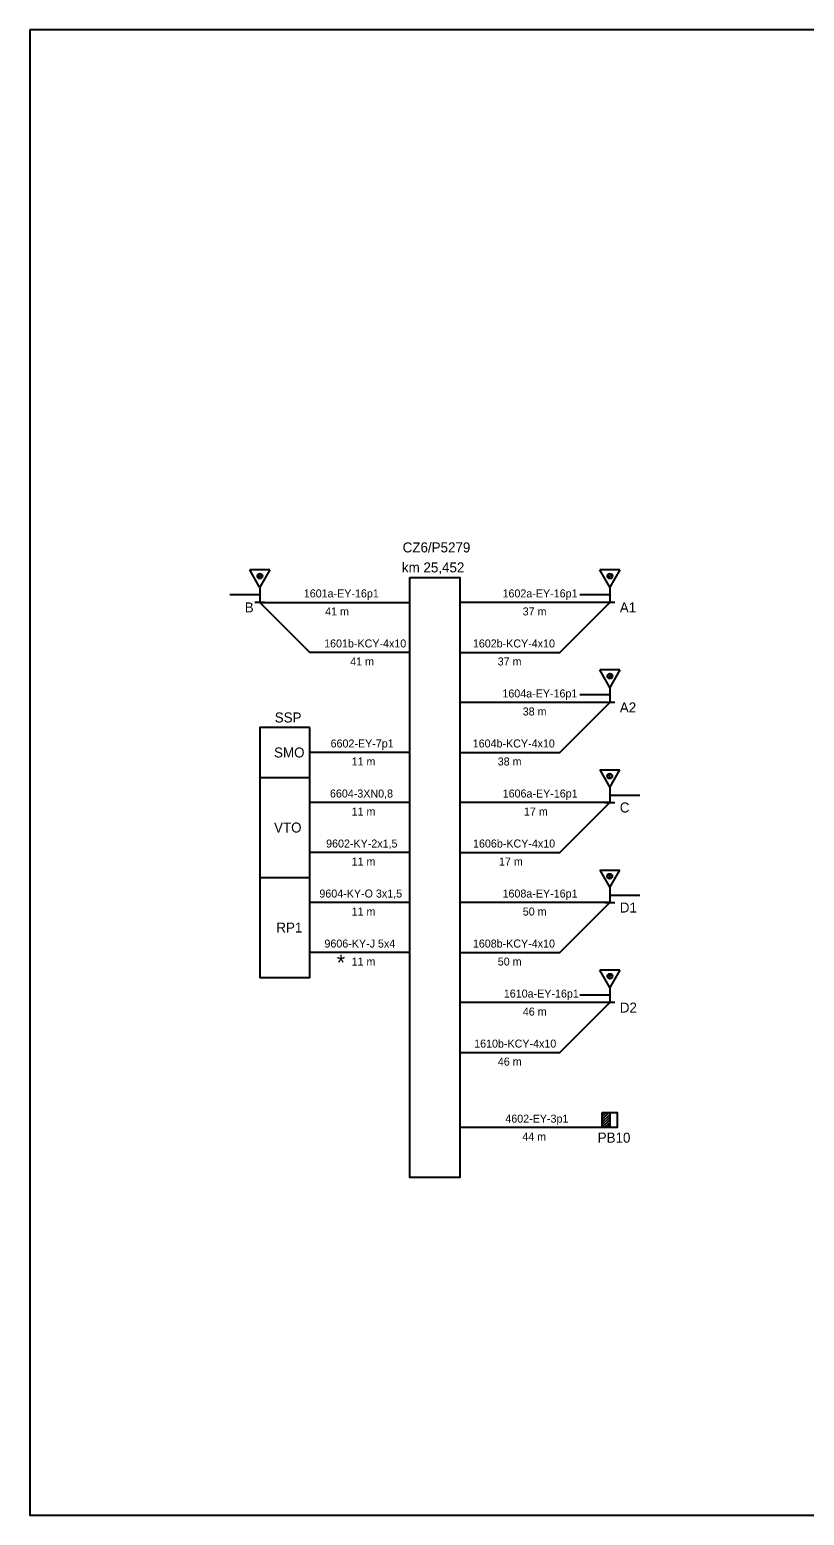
# Model space of a CAD drawing. Extents: x -650084 to -649664, y -1160055 to -1159758.
# Drawn here: x -650084 to -649929.1, y -1160054.5 to -1159757.5 of the extents above; entities that cross this region are included whole.
import ezdxf

# ---------------------------------------------------------------- set-up
doc = ezdxf.new("R2010")
doc.units = 0
doc.layers.add('Rámečky-tisk', color=7, linetype='Continuous')
doc.layers.add('Vrstva 1', color=7, linetype='Continuous')

msp = doc.modelspace()

# ---------------------------------------------------------------- linework, layer by layer
at = {"layer": 'Rámečky-tisk'}
msp.add_line((-649664, -1159757.5), (-650084, -1159757.5), dxfattribs=at)
msp.add_lwpolyline([(-650084, -1159757.5), (-650084, -1160054.5), (-649664, -1160054.5)], dxfattribs=at)
at = {"layer": 'Vrstva 1'}
for p, q in [((-650038.02, -1159868.98), (-650040, -1159865.5)), ((-650036, -1159865.5), (-650040, -1159865.5)), ((-650038.48, -1159866.76), (-650037.95, -1159866.23)), ((-650038.3, -1159867.11), (-650037.6, -1159866.41)), ((-650036, -1159865.5), (-650037.98, -1159868.98)), ((-650037.87, -1159867.21), (-650037.5, -1159866.84)), ((-649968.02, -1159868.98), (-649970, -1159865.5)), ((-649966, -1159865.5), (-649970, -1159865.5)), ((-649968.48, -1159866.76), (-649967.95, -1159866.23)), ((-649968.3, -1159867.11), (-649967.6, -1159866.41)), ((-649966, -1159865.5), (-649967.98, -1159868.98)), ((-649967.87, -1159867.21), (-649967.5, -1159866.84)), ((-650038, -1159870.5), (-650044, -1159870.5)), ((-650038, -1159869), (-650038, -1159872)), ((-649968, -1159870.5), (-649974, -1159870.5)), ((-649968, -1159869), (-649968, -1159872)), ((-650037, -1159872), (-650039, -1159872)), ((-650038, -1159872), (-650008, -1159872)), ((-649968, -1159872), (-649998, -1159872)), ((-649967, -1159872), (-649969, -1159872)), ((-649968.02, -1159888.98), (-649970, -1159885.5)), ((-649966, -1159885.5), (-649970, -1159885.5)), ((-649966, -1159885.5), (-649967.98, -1159888.98)), ((-649968.48, -1159886.76), (-649967.95, -1159886.23)), ((-649968.3, -1159887.11), (-649967.6, -1159886.41)), ((-649967.87, -1159887.21), (-649967.5, -1159886.84)), ((-649968, -1159890.5), (-649974, -1159890.5)), ((-649968, -1159889), (-649968, -1159892)), ((-649968, -1159892), (-649998, -1159892)), ((-649967, -1159892), (-649969, -1159892)), ((-650008, -1159902), (-650028, -1159902)), ((-649970, -1159905.5), (-649966, -1159905.5)), ((-649970, -1159905.5), (-649968.02, -1159908.98)), ((-649967.7, -1159907.11), (-649968.4, -1159906.41)), ((-649967.52, -1159906.76), (-649968.05, -1159906.23)), ((-649967.98, -1159908.98), (-649966, -1159905.5)), ((-650038, -1159907), (-650028, -1159907)), ((-649968.13, -1159907.21), (-649968.5, -1159906.84)), ((-649968, -1159909), (-649968, -1159912)), ((-650008, -1159912), (-650028, -1159912)), ((-649968, -1159912), (-649998, -1159912)), ((-649969, -1159912), (-649967, -1159912)), ((-649968, -1159910.5), (-649962, -1159910.5)), ((-650008, -1159922), (-650028, -1159922)), ((-650038, -1159927), (-650028, -1159927)), ((-649970, -1159925.5), (-649966, -1159925.5)), ((-649970, -1159925.5), (-649968.02, -1159928.98)), ((-649968.13, -1159927.21), (-649968.5, -1159926.84)), ((-649967.7, -1159927.11), (-649968.4, -1159926.41)), ((-649967.52, -1159926.76), (-649968.05, -1159926.23)), ((-649967.98, -1159928.98), (-649966, -1159925.5)), ((-649968, -1159929), (-649968, -1159932)), ((-649968, -1159930.5), (-649962, -1159930.5)), ((-650008, -1159932), (-650028, -1159932)), ((-649968, -1159932), (-649998, -1159932)), ((-649969, -1159932), (-649967, -1159932)), ((-650008, -1159942), (-650028, -1159942)), ((-649968.02, -1159948.98), (-649970, -1159945.5)), ((-649966, -1159945.5), (-649970, -1159945.5)), ((-649968.48, -1159946.76), (-649967.95, -1159946.23)), ((-649968.3, -1159947.11), (-649967.6, -1159946.41)), ((-649966, -1159945.5), (-649967.98, -1159948.98)), ((-649967.87, -1159947.21), (-649967.5, -1159946.84)), ((-649968, -1159950.5), (-649974, -1159950.5)), ((-649968, -1159949), (-649968, -1159952)), ((-649968, -1159952), (-649998, -1159952)), ((-649967, -1159952), (-649969, -1159952)), ((-649969.5, -1159974.26), (-649969.24, -1159974)), ((-649969.5, -1159974.79), (-649968.71, -1159974)), ((-649969.5, -1159975.32), (-649968.18, -1159974)), ((-649969.5, -1159975.85), (-649968, -1159974.35)), ((-649969.5, -1159976.38), (-649968, -1159974.88)), ((-649968, -1159977), (-649998, -1159977)), ((-649969.5, -1159976.91), (-649968, -1159975.41)), ((-649969.06, -1159977), (-649968, -1159975.94)), ((-649968.53, -1159977), (-649968, -1159976.47))]:
    msp.add_line(p, q, dxfattribs=at)
for points in [[(-650008, -1159867), (-649998, -1159867), (-649998, -1159987), (-650008, -1159987)], [(-650028, -1159897), (-650038, -1159897), (-650038, -1159947), (-650028, -1159947)], [(-649969.5, -1159974), (-649968, -1159974), (-649968, -1159977), (-649969.5, -1159977)], [(-649969.5, -1159974), (-649968, -1159974), (-649968, -1159977), (-649969.5, -1159977)], [(-649969.5, -1159974), (-649966.5, -1159974), (-649966.5, -1159977), (-649969.5, -1159977)]]:
    msp.add_lwpolyline(points, close=True, dxfattribs=at)
for points in [[(-650008, -1159882), (-650028, -1159882), (-650038, -1159872)], [(-649998, -1159882), (-649978, -1159882), (-649968, -1159872)], [(-649998, -1159902), (-649978, -1159902), (-649968, -1159892)], [(-649998, -1159922), (-649978, -1159922), (-649968, -1159912)], [(-649998, -1159942), (-649978, -1159942), (-649968, -1159932)], [(-649998, -1159962), (-649978, -1159962), (-649968, -1159952)]]:
    msp.add_lwpolyline(points, dxfattribs=at)
for centre in [(-650037.98, -1159866.73), (-649967.98, -1159866.73), (-649967.98, -1159886.73), (-649968.02, -1159906.73), (-649968.02, -1159926.73), (-649967.98, -1159946.73)]:
    msp.add_circle(centre, 0.5, dxfattribs=at)

# ---------------------------------------------------------------- texts
for s, height, p in [('CZ6/P5279', 2, (-650009.42, -1159862)), ('km 25,452', 2, (-650009.57, -1159866)), ('1601a-EY-16p1', 1.6, (-650029.19, -1159871)), ('1602a-EY-16p1', 1.6, (-649989.45, -1159871)), ('B', 2, (-650041, -1159874)), ('41 m  ', 1.6, (-650024.92, -1159874.6)), ('37 m  ', 1.6, (-649985.42, -1159874.6)), ('A1', 2, (-649966, -1159874)), ('1601b-KCY-4x10', 1.6, (-650025.12, -1159881)), ('1602b-KCY-4x10', 1.6, (-649995.38, -1159881)), ('41 m  ', 1.6, (-650019.92, -1159884.6)), ('37 m  ', 1.6, (-649990.42, -1159884.6)), ('1604a-EY-16p1', 1.6, (-649989.48, -1159891)), ('SSP', 2, (-650035, -1159896)), ('38 m  ', 1.6, (-649985.41, -1159894.6)), ('A2', 2, (-649966, -1159894)), ('6602-EY-7p1', 1.6, (-650023.83, -1159901)), ('1604b-KCY-4x10', 1.6, (-649995.41, -1159901)), ('SMO', 2, (-650035.14, -1159903)), ('11 m  ', 1.6, (-650019.63, -1159904.6)), ('38 m  ', 1.6, (-649990.41, -1159904.6)), ('6604-3XN0,8', 1.6, (-650023.96, -1159911)), ('1606a-EY-16p1', 1.6, (-649989.42, -1159911)), ('C', 2, (-649966, -1159914)), ('11 m  ', 1.6, (-650019.63, -1159914.6)), ('17 m  ', 1.6, (-649985.16, -1159914.6)), ('VTO', 2, (-650035.14, -1159918)), ('9602-KY-2x1,5', 1.6, (-650024.73, -1159921)), ('1606b-KCY-4x10', 1.6, (-649995.35, -1159921)), ('11 m  ', 1.6, (-650019.63, -1159924.6)), ('17 m  ', 1.6, (-649990.16, -1159924.6)), ('9604-KY-O 3x1,5', 1.6, (-650026.07, -1159931)), ('1608a-EY-16p1', 1.6, (-649989.45, -1159931)), ('11 m  ', 1.6, (-650019.63, -1159934.6)), ('50 m  ', 1.6, (-649985.4, -1159934.6)), ('D1', 2, (-649966, -1159934)), ('RP1', 2, (-650034.68, -1159938)), ('9606-KY-J 5x4', 1.6, (-650025.06, -1159941)), ('1608b-KCY-4x10', 1.6, (-649995.38, -1159941)), ('*', 3.2, (-650022.6, -1159945.6)), ('11 m  ', 1.6, (-650019.63, -1159944.6)), ('50 m  ', 1.6, (-649990.4, -1159944.6)), ('1610a-EY-16p1', 1.6, (-649989.19, -1159951)), ('46 m  ', 1.6, (-649985.39, -1159954.6)), ('D2', 2, (-649966, -1159954)), ('1610b-KCY-4x10', 1.6, (-649995.12, -1159961)), ('46 m  ', 1.6, (-649990.39, -1159964.6)), ('4602-EY-3p1', 1.6, (-649988.89, -1159976)), ('44 m  ', 1.6, (-649985.5, -1159979.6)), ('PB10', 2, (-649970.42, -1159980))]:
    msp.add_text(s, height=height, dxfattribs=at).set_placement(p)

doc.saveas('drawing.dxf')
